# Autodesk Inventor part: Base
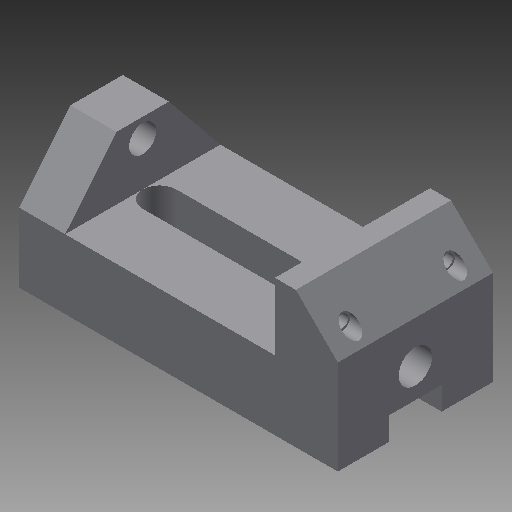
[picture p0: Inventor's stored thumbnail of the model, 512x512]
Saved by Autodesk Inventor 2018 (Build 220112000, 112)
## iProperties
Shininess: 77.0
Length Units: 11269
Angle Units: 11279
Time Units: 11290
Mass Units: 11283
Length Display Precision: 3
Angle Display Precision: 2
Created: 2002-02
Part Number: Base
Document SubType Name: Modeling
Designer: ***
Density: 1 g/cm^3
Material: Generic
Appearance: Default
Density: 0.0
Volumn: 0.0
Area: 0.0
PropertySet Name: Model Information
Control State: 0
Master: False
Checked Out: False
Author: ***
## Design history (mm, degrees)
sketch "Sketch2"
  geometry: L1 (-63.961, -4.254)-(-63.961, -37.254); L2 (-63.961, -37.254)-(88.039, -37.254); L3 (88.039, -37.254)-(88.039, 7.746); L4 (88.039, 7.746)-(68.039, 27.746); L5 (68.039, 27.746)-(58.039, 27.746); L6 (58.039, 27.746)-(58.039, -4.254); L7 (58.039, -4.254)-(-63.961, -4.254)
  constraints: 14 end point, 4 parallel, 1 perpendicular, 1 vertical
  dimensions: "d7" = 10 distance of L4.end L5.end; "d8" = 135 deg angle of L3 L4; "d9" = 33 distance of L1.start L1.end; "d10" = 152 distance of L1.end L2.end; "d11" = 65 distance between parallel lines of L5 L2; "d21" = 30 distance between parallel lines of L3 L6
extrude "Extrusion1" new body sketch "Sketch2" stored distance "d13" = 74; taper "d14" = 0 deg
sketch "Sketch3"
  geometry: L1 (0, 74)-(0, 0) reference; L2 (0, 0)-(-30, 24.5); L3 (-30, 24.5)-(-30, 49.5); L4 (-30, 49.5)-(0, 74); C1 r 6.5 at (-21, 37)
  constraints: 6 end point, 1 centre point, 1 equal length, 1 parallel
  dimensions: "d15" = 25 distance of L2.end L3.end; "d16" = 30 distance between parallel lines of L3 L1; "d17" = 13 diameter of C1; "d18" = 9 distance from line of L3 C1.centre
extrude "Extrusion2" join sketch "Sketch3" distance "d19" = 22; taper "d20" = 0 deg
sketch "Sketch4"
  geometry: L1 (0, 0)-(0, 74) reference; L2 (0, 0)-(45, 0) reference; C1 r 8 at (25, 37)
  constraints: 1 centre point
  dimensions: "d22" = 16 diameter of C1; "d23" = 25 distance from line of L1 C1.centre; "d24" = 37 distance from line of L2 C1.centre
extrude "Extrusion3" cut sketch "Sketch4" distance "d25" = 13; taper "d26" = 0 deg
sketch "Sketch5"
  geometry: L1 (45, 74)-(0, 74) reference; L2 (65, 0)-(65, 74) reference; 1 further point
  dimensions: "d27" = 12 distance from line of point (51, 62) L1; "d28" = 14 distance from line of L2 point (51, 62)
hole "Hole1" sketch "Sketch5" at (51, 62) diameter "d29" = 6; stored, may be unused: countersink angle "d33" = 82 deg, drill point angle "d35" = 0 deg; dims "d30" = 6, "d31" = 8, "d32" = 10, "d34" = 30
mirror "Mirror1"
sketch "Sketch6"
  geometry: L1 (100, 0)-(100, 74) reference; L2 (100, 74)-(0, 74) reference; L3 (14, 45)-(92, 45); L4 (92, 29)-(14, 29); A1 r 8 centre (92, 37) between (92, 29) and (92, 45); A2 r 8 centre (14, 37) between (14, 45) and (14, 29)
  constraints: 4 end point, 4 point on circle, 4 tangent, 2 centre point, 1 horizontal, 1 parallel
  dimensions: "d36" = 8 radius of A2; "d37" = 78 distance of L4.start L4.end; "d38" = 8 distance from line of L1 A1.centre; "d39" = 37 distance from line of L2 A2.centre
extrude "Extrusion4" cut sketch "Sketch6" extent not by distance; stored distance "d40" = 13; taper "d41" = 0 deg
sketch "Sketch7"
  geometry: L1 (0, 49.5)-(11, 49.5); L2 (11, 49.5)-(11, 24.5); L3 (11, 24.5)-(0, 24.5); L4 (0, 24.5)-(0, 49.5); L5 (45, 74)-(0, 74) reference; L6 (0, 0)-(0, 74) reference
  constraints: 8 end point, 2 parallel, 1 collinear, 1 horizontal, 1 perpendicular
  dimensions: "d42" = 25 distance of L3.end L1.start; "d43" = 11 distance of L1.start L1.end; "d44" = 24.5 distance between parallel lines of L5 L1
extrude "Extrusion5" cut sketch "Sketch7" extent not by distance; stored distance "d45" = 13; taper "d46" = 0 deg
body "Solid1"
